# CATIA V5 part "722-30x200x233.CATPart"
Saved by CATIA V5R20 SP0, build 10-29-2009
Part number: 722-30x200x233
Definition: NONE
Nomenclature: 722-30x200x233
Source: Unknown
Description: 722-30x200x233
Bounding box of the stored display mesh (mm): x -15 to 15, y -15 to 15, z -185 to 48
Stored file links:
  C:\Users\Utente\Desktop\IO LAVORO\3D X SITO CF\X SITO\722\722-30x200x233.CATPart
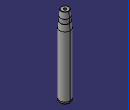
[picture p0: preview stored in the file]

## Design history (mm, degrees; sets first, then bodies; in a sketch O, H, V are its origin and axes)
Body1 "722-30x200x233" (main body)
  Solid1: solid without history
